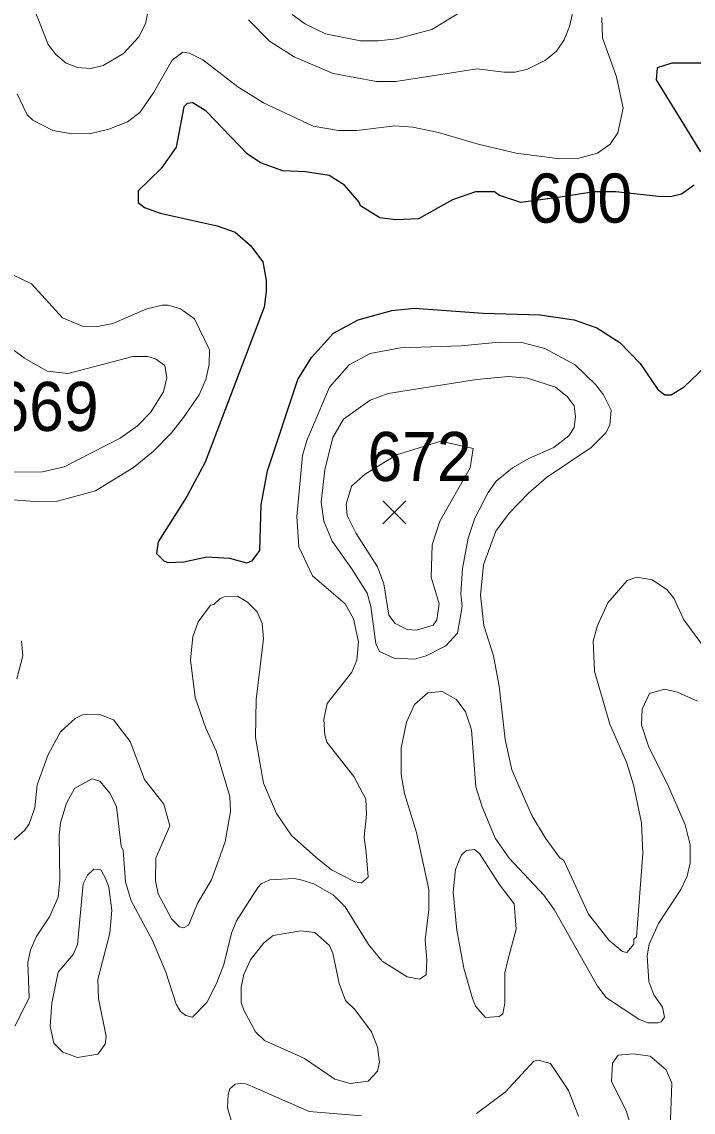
# Model space of a CAD drawing. Extents: x 423 to 448.8, y 7456.3 to 7484.
# Drawn here: x 436.858 to 437.952, y 7465.699 to 7467.476 of the extents above; entities that cross this region are included whole.
import ezdxf
from ezdxf.enums import TextEntityAlignment as Align

# ---------------------------------------------------------------- set-up
doc = ezdxf.new("R2010")
doc.units = 0
doc.header["$LTSCALE"] = 0.032
for name, color, linetype, lineweight in [('1', 7, 'Continuous', 25), ('2', 7, 'Continuous', 13), ('21', 7, 'Continuous', 25)]:
    doc.layers.add(name, color=color, linetype=linetype, lineweight=lineweight)
doc.layers.add('61', color=7, linetype='Continuous')

msp = doc.modelspace()

# ---------------------------------------------------------------- linework, layer by layer
at = {"layer": '1'}
for points in [[(437.9936, 7467.4091), (437.917, 7467.4091), (437.893, 7467.4013), (437.8915, 7467.382), (437.9634, 7467.2644)], [(437.9533, 7467.2103), (437.9325, 7467.1956), (437.917, 7467.1917), (437.9, 7467.1909), (437.8257, 7467.1995), (437.7904, 7467.1992), (437.7348, 7467.1908), (437.6709, 7467.1817), (437.636, 7467.1933), (437.6277, 7467.1995), (437.5968, 7467.1995), (437.5597, 7467.1863), (437.504, 7467.1554), (437.4669, 7467.1538), (437.4413, 7467.1569), (437.4096, 7467.1762), (437.4073, 7467.1825), (437.3833, 7467.2103), (437.3586, 7467.2258), (437.3199, 7467.232), (437.2828, 7467.2335), (437.2464, 7467.2467), (437.2247, 7467.2613), (437.1582, 7467.3309), (437.1366, 7467.3441), (437.1273, 7467.3433), (437.1218, 7467.3379), (437.1095, 7467.2722), (437.0847, 7467.2374), (437.0476, 7467.201), (437.0476, 7467.1817), (437.0577, 7467.1739), (437.0832, 7467.1647), (437.176, 7467.1438), (437.2054, 7467.1337), (437.2301, 7467.112), (437.2503, 7467.085), (437.2557, 7467.0556), (437.2557, 7467.0371), (437.2526, 7467.0115), (437.1567, 7466.7586), (437.1265, 7466.7029), (437.0801, 7466.6287), (437.077, 7466.6101), (437.0894, 7466.5977), (437.0956, 7466.5954), (437.1219, 7466.5962), (437.159, 7466.6047), (437.1961, 7466.6024), (437.224, 7466.5946), (437.2333, 7466.5977), (437.2456, 7466.6147), (437.2479, 7466.689), (437.258, 7466.7447), (437.3075, 7466.8932), (437.3299, 7466.9295), (437.3655, 7466.969), (437.4057, 7466.9906), (437.4607, 7467.0061), (437.4978, 7467.0099), (437.6092, 7467.0015), (437.702, 7466.9991), (437.7577, 7466.9906), (437.7948, 7466.9775), (437.8319, 7466.9535), (437.8652, 7466.9194), (437.8938, 7466.8769), (437.9054, 7466.8684), (437.9155, 7466.8684), (437.9371, 7466.8816), (438.0167, 7466.9574)]]:
    msp.add_lwpolyline(points, dxfattribs=at)
at = {"layer": '2'}
for points in [[(437.227, 7467.4795), (437.2611, 7467.4446), (437.3013, 7467.4191), (437.3648, 7467.392), (437.4359, 7467.3789), (437.4669, 7467.3789), (437.5999, 7467.3998), (437.6432, 7467.3944), (437.6618, 7467.3944), (437.6819, 7467.399), (437.7112, 7467.4137), (437.729, 7467.4284), (437.7414, 7467.447), (437.7499, 7467.4686), (437.7592, 7467.5089)], [(436.879, 7467.4949), (436.9007, 7467.4392), (436.913, 7467.423), (436.9301, 7467.4091), (436.9486, 7467.4021), (436.9703, 7467.4005), (436.9904, 7467.4052), (437.0236, 7467.4245), (437.0484, 7467.4516), (437.0592, 7467.4733), (437.0654, 7467.5027)], [(437.2982, 7467.488), (437.3198, 7467.4725), (437.3524, 7467.457), (437.4096, 7467.4454), (437.439, 7467.4454), (437.4684, 7467.4485), (437.5256, 7467.464), (437.5743, 7467.4934)], [(437.8025, 7467.4833), (437.804, 7467.4501), (437.8265, 7467.3867), (437.8373, 7467.3356), (437.8288, 7467.2954), (437.8164, 7467.2768), (437.7955, 7467.2621)], [(437.7955, 7467.2621), (437.7654, 7467.2544), (437.7345, 7467.2528), (437.6633, 7467.2621), (437.6014, 7467.2768), (437.5365, 7467.2961), (437.4947, 7467.3047), (437.4653, 7467.307), (437.4034, 7467.2992), (437.374, 7467.2992), (437.3323, 7467.3062), (437.2518, 7467.3441), (437.21, 7467.3704), (437.1528, 7467.4145), (437.1312, 7467.4253), (437.1203, 7467.4268), (437.1025, 7467.4137), (437.0723, 7467.3604), (437.0499, 7467.3286), (437.0298, 7467.3132), (436.9997, 7467.3016), (436.9703, 7467.2946), (436.9394, 7467.2938), (436.9084, 7467.2992), (436.8759, 7467.3162), (436.8666, 7467.3247), (436.8504, 7467.3588)], [(436.8434, 7467.0641), (436.8736, 7467.0494), (436.9239, 7466.9937), (436.9564, 7466.9806), (436.9811, 7466.9798), (437.0059, 7466.9845), (437.0616, 7467.0084), (437.0863, 7467.0146), (437.0963, 7467.0146), (437.1164, 7467.0084), (437.1389, 7466.9922), (437.1636, 7466.9419), (437.1628, 7466.9179), (437.1575, 7466.8932), (437.1466, 7466.8684), (437.1211, 7466.8313), (437.1017, 7466.8066), (437.0716, 7466.7764), (437.0399, 7466.7501), (436.978, 7466.7122), (436.9161, 7466.6952), (436.879, 7466.6944), (436.8295, 7466.6983)], [(437.2394, 7466.3719), (437.2386, 7466.31), (437.2518, 7466.2358), (437.2727, 7466.1863), (437.2974, 7466.1506), (437.3369, 7466.115), (437.3624, 7466.0942), (437.4003, 7466.0748), (437.4111, 7466.0733), (437.422, 7466.0826), (437.4189, 7466.1228), (437.4158, 7466.1476), (437.4196, 7466.1847), (437.4181, 7466.2095), (437.3987, 7466.2466), (437.3547, 7466.3023), (437.3516, 7466.3146), (437.35, 7466.3394), (437.3555, 7466.3656), (437.3957, 7466.4167), (437.4034, 7466.436), (437.4065, 7466.4662), (437.398, 7466.5034), (437.3848, 7466.5281), (437.3315, 7466.5737), (437.3091, 7466.6209), (437.306, 7466.6704), (437.3152, 7466.7694), (437.3222, 7466.7942), (437.3593, 7466.8808), (437.391, 7466.9171), (437.4251, 7466.9357), (437.4746, 7466.945), (437.5736, 7466.9481), (437.6355, 7466.9543), (437.6726, 7466.9535), (437.7097, 7466.9442), (437.7592, 7466.9171), (437.7932, 7466.8847), (437.8056, 7466.8684), (437.818, 7466.8437), (437.8156, 7466.8189), (437.8095, 7466.8066), (437.7855, 7466.7826), (437.7128, 7466.7338), (437.6834, 7466.7083), (437.6517, 7466.6758), (437.63, 7466.6464), (437.6099, 7466.5915), (437.6053, 7466.542), (437.6107, 7466.4925), (437.6262, 7466.443), (437.6355, 7466.3935), (437.6455, 7466.3069), (437.6563, 7466.2574), (437.6888, 7466.1832), (437.7112, 7466.146), (437.7337, 7466.1143), (437.7406, 7466.1096), (437.7808, 7466.0223), (437.8149, 7465.979), (437.8365, 7465.9611), (437.8435, 7465.9596), (437.8551, 7465.9735), (437.8551, 7465.9813), (437.859, 7465.9851), (437.8698, 7466.1213), (437.8675, 7466.1708), (437.8543, 7466.2327), (437.8427, 7466.2698), (437.8156, 7466.3317), (437.7909, 7466.4183), (437.7886, 7466.4678), (437.7955, 7466.4925), (437.8126, 7466.5297), (437.8443, 7466.566), (437.8598, 7466.5714), (437.8845, 7466.5668), (437.9085, 7466.5513), (437.9201, 7466.5374), (437.9363, 7466.5018), (437.9719, 7466.4538)], [(436.8233, 7466.7423), (436.8914, 7466.7431), (436.927, 7466.7509), (437.0182, 7466.798), (437.046, 7466.8181), (437.0677, 7466.8398), (437.0886, 7466.8731), (437.094, 7466.8963), (437.0909, 7466.9164), (437.0755, 7466.9272), (437.0631, 7466.9311), (437.0384, 7466.9311), (436.9332, 7466.9032), (436.8991, 7466.9071), (436.862, 7466.928), (436.8365, 7466.9473)], [(436.8342, 7466.1336), (436.8628, 7466.1591), (436.8697, 7466.1692), (436.879, 7466.1955), (436.8829, 7466.2327), (436.9006, 7466.2822), (436.9207, 7466.3193), (436.9447, 7466.3409), (436.9564, 7466.3471), (436.9834, 7466.3479), (437.0074, 7466.3386), (437.0345, 7466.3038), (437.0577, 7466.2419), (437.0894, 7466.2017), (437.0987, 7466.1661), (437.0762, 7466.1135), (437.0755, 7466.0764), (437.0801, 7466.0555), (437.1017, 7466.0145), (437.1149, 7466.0014), (437.1211, 7465.9998), (437.1296, 7466.0044), (437.1443, 7466.0408), (437.1667, 7466.078), (437.1891, 7466.1398), (437.1977, 7466.1893), (437.1969, 7466.2141), (437.1745, 7466.2883), (437.1574, 7466.3255), (437.1404, 7466.375), (437.1327, 7466.4369), (437.1365, 7466.474), (437.145, 7466.4987), (437.1652, 7466.5258), (437.1706, 7466.5266), (437.1807, 7466.5366), (437.1892, 7466.5397), (437.2093, 7466.5405), (437.2255, 7466.5304), (437.241, 7466.5149), (437.2495, 7466.4956), (437.2518, 7466.4709), (437.2394, 7466.3719)], [(436.8574, 7466.4678), (436.8597, 7466.443), (436.8496, 7466.4059)], [(437.9588, 7466.3695), (437.9263, 7466.3842), (437.9046, 7466.3889), (437.8806, 7466.3819), (437.8682, 7466.3564), (437.8675, 7466.3309), (437.8791, 7466.2945), (437.91, 7466.2342), (437.9387, 7466.1677), (437.9464, 7466.1352), (437.9464, 7466.1058), (437.9417, 7466.0842), (437.9317, 7466.0625), (437.8953, 7466.0068), (437.8799, 7465.9735), (437.8768, 7465.9542), (437.8791, 7465.9124), (437.8876, 7465.8908), (437.9015, 7465.8707), (437.9046, 7465.8544), (437.8992, 7465.8467), (437.8938, 7465.8451), (437.8775, 7465.8451), (437.8629, 7465.8513), (437.8103, 7465.8861), (437.7955, 7465.9047), (437.7251, 7466.03), (437.7081, 7466.0532), (437.6517, 7466.1135), (437.6292, 7466.146), (437.6076, 7466.1971), (437.5975, 7466.2296), (437.5906, 7466.3224), (437.5805, 7466.3518), (437.5658, 7466.3718), (437.5426, 7466.385), (437.5194, 7466.3827), (437.4978, 7466.3641), (437.4846, 7466.3348), (437.4761, 7466.293), (437.4761, 7466.2497), (437.4815, 7466.2187), (437.5008, 7466.1553), (437.521, 7466.0625), (437.521, 7466.03), (437.5148, 7465.9805), (437.5179, 7465.948), (437.5163, 7465.9232), (437.5055, 7465.9163), (437.4854, 7465.9201), (437.4451, 7465.9457), (437.4227, 7465.9728), (437.3848, 7466.0339), (437.3655, 7466.0532), (437.3338, 7466.0717), (437.3122, 7466.0779), (437.3013, 7466.0803), (437.2619, 7466.0779), (437.2479, 7466.0718), (437.2425, 7466.0656), (437.2077, 7466.0114), (437.1992, 7465.9913), (437.1869, 7465.9403), (437.1752, 7465.9094), (437.159, 7465.8784), (437.1358, 7465.8544), (437.125, 7465.8568), (437.1165, 7465.8637), (437.1095, 7465.8753), (437.0925, 7465.9279), (437.0708, 7465.979)], [(437.0708, 7465.979), (437.036, 7466.0439), (437.0267, 7466.0749), (437.0229, 7466.1259), (437.0197, 7466.1329), (437.012, 7466.1971), (437.002, 7466.2187), (436.985, 7466.2388), (436.9718, 7466.2427), (436.9439, 7466.2272), (436.9308, 7466.2033), (436.9208, 7466.1708), (436.9184, 7466.1507), (436.92, 7466.078), (436.9169, 7466.0501), (436.903, 7466.0176), (436.8813, 7465.9852), (436.872, 7465.9635), (436.8674, 7465.9434), (436.8697, 7465.8861), (436.8465, 7465.8397)], [(437.5983, 7465.6974), (437.6455, 7465.7322), (437.6919, 7465.7825), (437.6989, 7465.784), (437.719, 7465.7786), (437.7484, 7465.7346), (437.7646, 7465.6928)], [(437.8536, 7465.6634), (437.8427, 7465.7005), (437.8187, 7465.75), (437.8203, 7465.7794), (437.8296, 7465.7925), (437.8536, 7465.7948), (437.8814, 7465.791), (437.9077, 7465.7685), (437.917, 7465.7469), (437.9139, 7465.6727)], [(437.2116, 7465.6448), (437.193, 7465.7067), (437.1938, 7465.7284), (437.1969, 7465.7376), (437.2054, 7465.7454), (437.2193, 7465.7469), (437.2333, 7465.7415), (437.3261, 7465.7005), (437.4112, 7465.6935)]]:
    msp.add_lwpolyline(points, dxfattribs=at)
for points in [[(437.5851, 7466.6349), (437.596, 7466.6673), (437.6177, 7466.7091), (437.6308, 7466.7276), (437.6571, 7466.7493), (437.685, 7466.7655), (437.7244, 7466.7826), (437.7491, 7466.8019), (437.7577, 7466.815), (437.76, 7466.8329), (437.7577, 7466.8506), (437.7468, 7466.8653), (437.7275, 7466.8808), (437.6819, 7466.8955), (437.6509, 7466.8986), (437.5983, 7466.8932), (437.4545, 7466.8707), (437.4251, 7466.8599), (437.3817, 7466.829), (437.3647, 7466.7988), (437.3516, 7466.7462), (437.3454, 7466.6936), (437.35, 7466.6627), (437.3632, 7466.6302), (437.3949, 7466.5854), (437.4204, 7466.5451), (437.4266, 7466.5235), (437.4343, 7466.4632), (437.4405, 7466.45), (437.4645, 7466.4391), (437.4978, 7466.4376), (437.5164, 7466.443), (437.5488, 7466.4593), (437.5674, 7466.4802), (437.5751, 7466.5235), (437.5728, 7466.5436), (437.5759, 7466.5854)], [(437.5263, 7466.624), (437.5387, 7466.6627), (437.5883, 7466.7493), (437.5929, 7466.781), (437.5404, 7466.7931), (437.4683, 7466.7706), (437.4172, 7466.7391), (437.3947, 7466.7196), (437.3864, 7466.6905), (437.388, 7466.672), (437.4026, 7466.6426), (437.4375, 7466.5884), (437.4475, 7466.5606), (437.456, 7466.5096), (437.4661, 7466.4956), (437.4854, 7466.4863), (437.5009, 7466.4848), (437.5279, 7466.4933), (437.5341, 7466.5018), (437.538, 7466.5281), (437.5248, 7466.5714)], [(437.6497, 7465.9472), (437.6633, 7465.9975), (437.6602, 7466.0392), (437.6355, 7466.071), (437.6037, 7466.1212), (437.5952, 7466.1275), (437.5821, 7466.1259), (437.5743, 7466.1189), (437.5643, 7466.095), (437.5604, 7466.0579), (437.5666, 7465.996), (437.5782, 7465.9341), (437.5921, 7465.8846), (437.5968, 7465.8722), (437.613, 7465.8536), (437.6355, 7465.8552), (437.6416, 7465.8598), (437.6447, 7465.8769), (437.6447, 7465.9264)], [(436.9818, 7465.9155), (437.0012, 7465.9913), (437.0043, 7466.0285), (436.9997, 7466.0656), (436.995, 7466.078), (436.9865, 7466.0942), (436.9749, 7466.0957), (436.9649, 7466.0857), (436.9579, 7466.0717), (436.9486, 7465.9728), (436.9416, 7465.9565), (436.9169, 7465.9279), (436.9069, 7465.8769), (436.9038, 7465.8397), (436.91, 7465.8118), (436.9246, 7465.7972), (436.9486, 7465.7887), (436.9819, 7465.7941), (436.9935, 7465.8103), (436.995, 7465.8227), (436.9826, 7465.8846)], [(437.3052, 7465.7929), (437.3183, 7465.7871), (437.3678, 7465.7531), (437.3926, 7465.7461), (437.4219, 7465.75), (437.4375, 7465.7662), (437.4405, 7465.781), (437.4375, 7465.8057), (437.4274, 7465.8305), (437.4003, 7465.8668), (437.3849, 7465.8815), (437.3748, 7465.9094), (437.3647, 7465.9589), (437.3593, 7465.9712), (437.3353, 7465.9921), (437.3122, 7465.9952), (437.2673, 7465.9875), (437.2518, 7465.9751), (437.2301, 7465.948), (437.2193, 7465.924), (437.2154, 7465.9032), (437.2154, 7465.8784), (437.2193, 7465.866), (437.2386, 7465.8304), (437.2533, 7465.8165)]]:
    msp.add_lwpolyline(points, close=True, dxfattribs=at)
at = {"layer": '21'}
for p, q in [((437.4457, 7466.6958), (437.4832, 7466.6583)), ((437.4832, 7466.6958), (437.4457, 7466.6583))]:
    msp.add_line(p, q, dxfattribs=at)

# ---------------------------------------------------------------- texts
at = {"layer": '61', "width": 0.95}
for s, p in [('600', (437.7674, 7467.1491)), ('669', (436.8981, 7466.8096)), ('672', (437.5059, 7466.728))]:
    msp.add_text(s, height=0.08, dxfattribs=at).set_placement(p, align=Align.CENTER)

doc.saveas('drawing.dxf')
